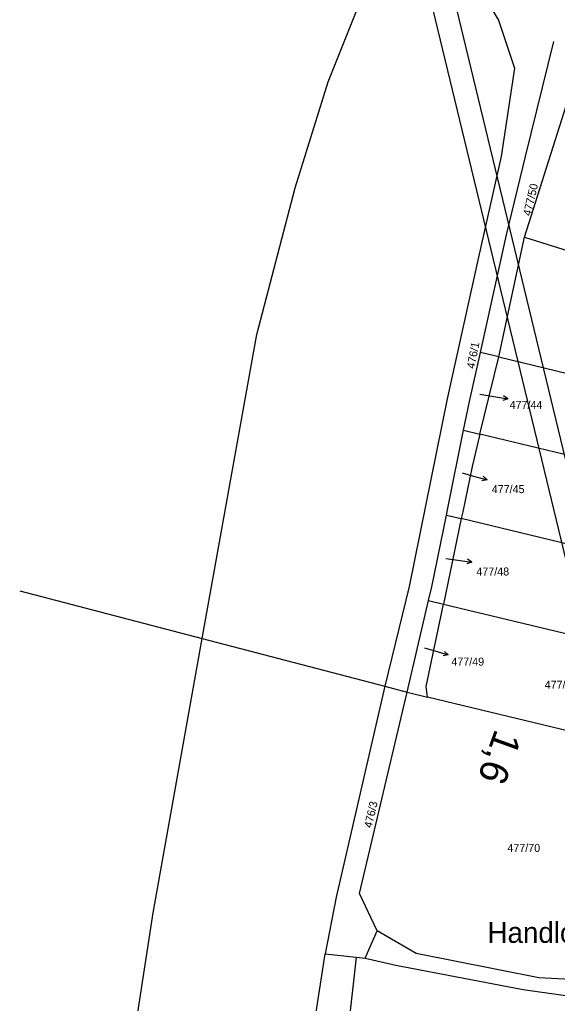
# Model space of a CAD drawing. Extents: x -738085 to -734306, y -1122197 to -1119753.
# Drawn here: x -735623.1 to -735509, y -1120522.6 to -1120313.6 of the extents above; entities that cross this region are included whole.
import ezdxf

# ---------------------------------------------------------------- set-up
doc = ezdxf.new("R2010")
doc.units = 0
for name, color, linetype in [('Hranice parcel', 7, 'Continuous'), ('Parcelní čísla', 7, 'Continuous'), ('Pop  PČ popisy', 7, 'Continuous'), ('Vrstva 1', 7, 'Continuous'), ('Vrstva 7', 7, 'Continuous')]:
    doc.layers.add(name, color=color, linetype=linetype)

msp = doc.modelspace()

# ---------------------------------------------------------------- linework, layer by layer
at = {"layer": 'Hranice parcel'}
for p, q in [((-735521.46, -1120385.26), (-735515.96, -1120359.84)), ((-735515.96, -1120359.84), (-735493.79, -1120366.81)), ((-735525.43, -1120401.67), (-735521.46, -1120385.26)), ((-735521.46, -1120385.26), (-735525.35, -1120384.33)), ((-735521.46, -1120385.26), (-735465.48, -1120398.66)), ((-735528.9, -1120400.84), (-735525.43, -1120401.67)), ((-735469.43, -1120415.11), (-735525.43, -1120401.67)), ((-735532.56, -1120418.84), (-735529.4, -1120419.6)), ((-735529.1, -1120418.17), (-735529.4, -1120419.6)), ((-735529.4, -1120419.6), (-735533.19, -1120437.76)), ((-735473.72, -1120432.96), (-735529.4, -1120419.6)), ((-735623.1, -1120434.93), (-735584.37, -1120445.06)), ((-735540.91, -1120456.47), (-735536.34, -1120437)), ((-735536.34, -1120437), (-735533.19, -1120437.76)), ((-735533.19, -1120437.76), (-735478, -1120451.01)), ((-735584.37, -1120445.06), (-735545.63, -1120455.18)), ((-735545.63, -1120455.18), (-735540.91, -1120456.47)), ((-735540.91, -1120456.47), (-735536.55, -1120457.52)), ((-735482.68, -1120470.47), (-735536.55, -1120457.52)), ((-735549.79, -1120512.96), (-735547.27, -1120507.12)), ((-735558.28, -1120512.02), (-735551.72, -1120512.75)), ((-735551.72, -1120512.75), (-735556.85, -1120559.89)), ((-735551.72, -1120512.75), (-735549.79, -1120512.96))]:
    msp.add_line(p, q, dxfattribs=at)
for points in [[(-735584.37, -1120445.06), (-735572.82, -1120380.46), (-735564.69, -1120349.32), (-735557.66, -1120326.8), (-735543.24, -1120290.61)], [(-735525.71, -1120306.7), (-735521.52, -1120313.69), (-735518.12, -1120323.94), (-735520.93, -1120342.67), (-735525.76, -1120364.03), (-735532.39, -1120394.14), (-735540.49, -1120433.99), (-735545.63, -1120455.18)], [(-735525.35, -1120384.33), (-735519.79, -1120359.29), (-735515.8, -1120342.7), (-735509.78, -1120318.28)], [(-735515.96, -1120359.84), (-735505.22, -1120325.91), (-735502.75, -1120322.57), (-735499.49, -1120320.43), (-735495.45, -1120319.9)], [(-735528.9, -1120400.84), (-735527.66, -1120394.71), (-735525.35, -1120384.33)], [(-735532.56, -1120418.84), (-735532.27, -1120417.41), (-735528.9, -1120400.84)], [(-735525.43, -1120401.67), (-735527.09, -1120408.51), (-735529.1, -1120418.17)], [(-735536.34, -1120437), (-735535.66, -1120434.11), (-735532.56, -1120418.84)], [(-735536.55, -1120457.52), (-735536.83, -1120455.22), (-735533.19, -1120437.76)], [(-735623.13, -1120737.75), (-735617.02, -1120668.92), (-735607.62, -1120586.63), (-735594.77, -1120503.3), (-735584.37, -1120445.06)], [(-735545.63, -1120455.18), (-735555.97, -1120500), (-735558.28, -1120512.02)], [(-735547.27, -1120507.12), (-735550.99, -1120499.24), (-735540.91, -1120456.47)], [(-735494.09, -1120518.1), (-735512.93, -1120517.17), (-735538.99, -1120511.95), (-735547.27, -1120507.12)], [(-735580.29, -1120761.53), (-735580.97, -1120726.38), (-735569.66, -1120585.92), (-735558.28, -1120512.02)], [(-735549.79, -1120512.96), (-735543.29, -1120514.47), (-735516.24, -1120519.64), (-735491.79, -1120523.07)]]:
    msp.add_lwpolyline(points, dxfattribs=at)
at = {"layer": 'Pop  PČ popisy'}
for p, q in [((-735525.48, -1120393.13), (-735522.49, -1120393.66)), ((-735522.49, -1120393.66), (-735519.54, -1120394.18)), ((-735519.54, -1120394.18), (-735520.43, -1120393.51)), ((-735519.54, -1120394.18), (-735520.61, -1120394.5)), ((-735529.23, -1120409.89), (-735526.82, -1120410.55)), ((-735526.82, -1120410.55), (-735523.92, -1120411.33)), ((-735523.92, -1120411.33), (-735524.76, -1120410.58)), ((-735523.92, -1120411.33), (-735525.02, -1120411.55)), ((-735532.68, -1120428.07), (-735530.16, -1120428.43)), ((-735530.16, -1120428.43), (-735527.19, -1120428.85)), ((-735527.19, -1120428.85), (-735528.25, -1120429.2)), ((-735527.19, -1120428.85), (-735528.11, -1120428.21)), ((-735537.19, -1120447.02), (-735535.02, -1120447.68)), ((-735535.02, -1120447.68), (-735532.15, -1120448.56)), ((-735532.15, -1120448.56), (-735532.96, -1120447.79)), ((-735532.15, -1120448.56), (-735533.25, -1120448.74))]:
    msp.add_line(p, q, dxfattribs=at)
at = {"layer": 'Vrstva 1'}
for points in [[(-734534.27, -1119984.39), (-735554.91, -1120230.88), (-735485.2, -1120519.57), (-734464.55, -1120273.08)], [(-734470.58, -1120269.4), (-735481.51, -1120513.53), (-735548.88, -1120234.56), (-734537.95, -1119990.43)]]:
    msp.add_lwpolyline(points, close=True, dxfattribs=at)

# ---------------------------------------------------------------- texts
at = {"layer": 'Parcelní čísla'}
for s, rotation, p in [('477/50', 77, (-735514.66, -1120355.42)), ('476/1', 79, (-735526.62, -1120387.86)), ('476/3', 77, (-735548.41, -1120485.4))]:
    msp.add_text(s, height=1.7, rotation=rotation, dxfattribs=at).set_placement(p)
for s, p in [('477/44', (-735519.14, -1120396.29)), ('477/45', (-735522.93, -1120414.18)), ('477/48', (-735526.19, -1120431.68)), ('477/49', (-735531.5, -1120450.82)), ('477/42', (-735511.7, -1120455.72)), ('477/70', (-735519.61, -1120490.39))]:
    msp.add_text(s, height=1.7, dxfattribs=at).set_placement(p)
at = {"layer": 'Pop  PČ popisy'}
msp.add_text('Handlovní', height=4.4, dxfattribs=at).set_placement((-735523.83, -1120509.71))
at = {"layer": 'Vrstva 7'}
msp.add_text('1,6', height=6, rotation=250.066, dxfattribs=at).set_placement((-735522.15, -1120464.09))

doc.saveas('drawing.dxf')
